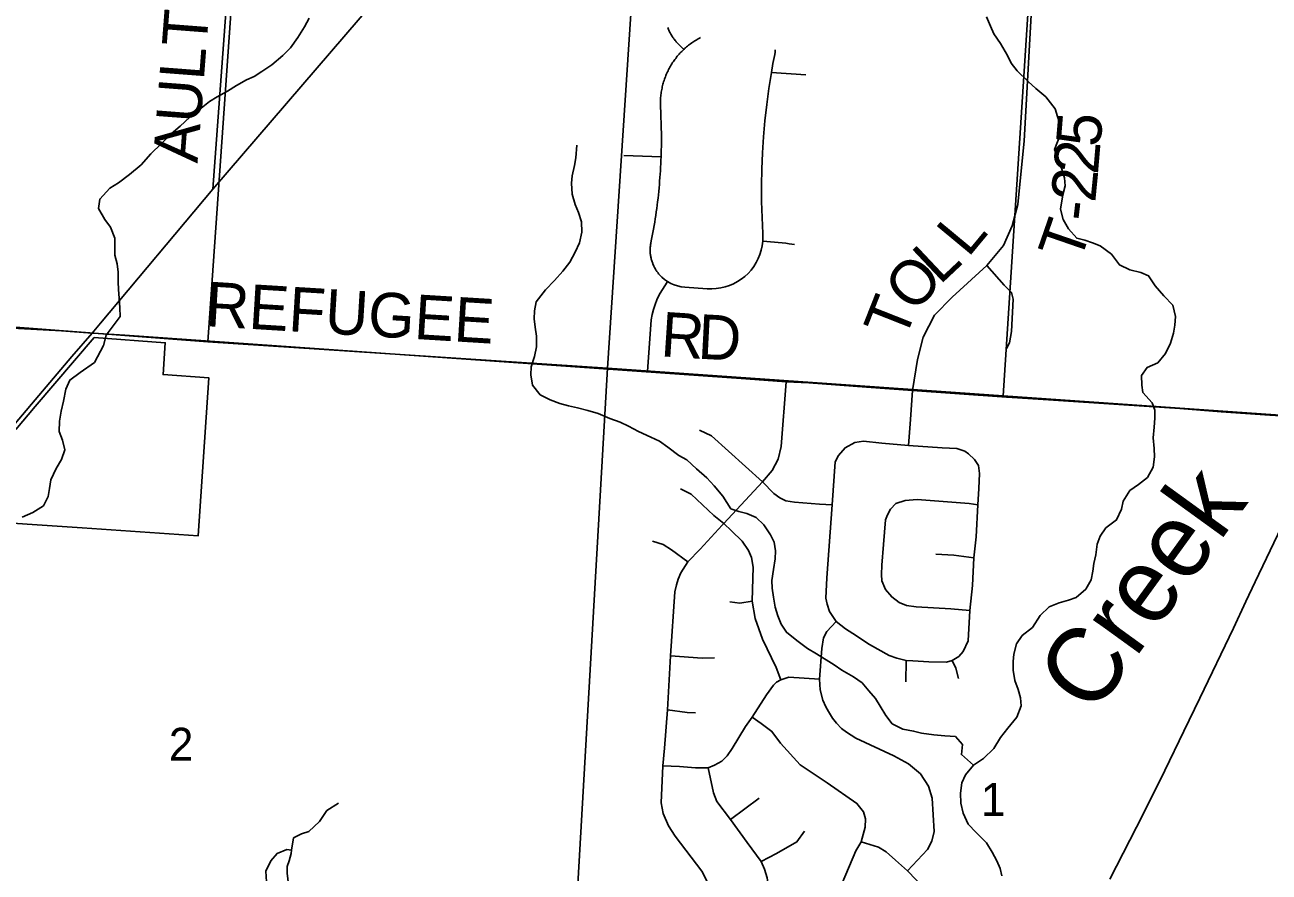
# Model space of a CAD drawing. Extents: x 0 to 34, y 0 to 22.
# Drawn here: x 6.46 to 8.044, y 15.327 to 16.406 of the extents above; entities that cross this region are included whole.
import ezdxf

# ---------------------------------------------------------------- set-up
doc = ezdxf.new("R2010")
doc.units = 0
for name, color, linetype in [('GM_X_Corporation', 7, 'Continuous'), ('GM_X_County_Road', 7, 'Continuous'), ('GM_X_County_Road_Text', 7, 'Continuous'), ('GM_X_Minor_Lake', 7, 'Continuous'), ('GM_X_Minor_River', 7, 'Continuous'), ('GM_X_Minor_River_Text', 7, 'Continuous'), ('GM_X_Section_Text', 7, 'Continuous'), ('GM_X_Township_Road', 7, 'Continuous'), ('GM_X_Township_Road_Text', 7, 'Continuous')]:
    doc.layers.add(name, color=color, linetype=linetype)

msp = doc.modelspace()

# ---------------------------------------------------------------- linework, layer by layer
at = {"layer": 'GM_X_Corporation'}
for points in [[(6.2535, 17.0548), (6.7642, 17.0207), (6.6929, 16.0021), (6.1806, 16.0412)], [(6.7642, 17.0207), (7.2687, 16.9868), (7.2018, 15.9686), (6.6929, 16.0021)], [(7.2687, 16.9868), (7.7715, 16.9516), (7.7055, 15.9334), (7.2018, 15.9686)], [(7.7715, 16.9516), (8.2797, 16.9169), (8.2166, 15.8976), (7.7055, 15.9334)], [(6.1806, 16.0412), (6.6929, 16.0021), (7.2018, 15.9686), (7.1441, 14.9641), (6.1096, 15.0446)], [(7.2018, 15.9686), (7.7055, 15.9334), (8.2166, 15.8976), (8.1497, 14.8881), (7.1441, 14.9641)]]:
    msp.add_lwpolyline(points, close=True, dxfattribs=at)
msp.add_lwpolyline([(6.3863, 15.7749), (6.5329, 15.7652), (6.6806, 15.7551), (6.694, 15.9564), (6.6358, 15.9605), (6.6386, 16.001), (6.5481, 16.0078), (6.4731, 15.9197), (6.4483, 15.8905)], dxfattribs=at)
at = {"layer": 'GM_X_County_Road'}
for points in [[(6.556, 16.0261), (6.6991, 16.1965), (6.9804, 16.5242), (7.026, 16.579), (7.046, 16.6041), (7.0557, 16.6231), (7.0747, 16.6658), (7.119, 16.7711), (7.177, 16.9074), (7.1885, 16.9354), (7.2006, 16.9746), (7.2668, 17.2151), (7.2825, 17.2751), (7.2901, 17.3083), (7.2922, 17.3236), (7.2973, 17.373), (7.3052, 17.4586), (7.3081, 17.496)], [(5.9168, 16.0609), (6.0471, 16.0509), (6.0534, 16.0504), (6.0669, 16.0492), (6.3448, 16.0254), (6.3457, 16.0254), (6.3647, 16.0237), (6.5064, 16.0163), (6.5453, 16.0133), (6.5533, 16.0128)], [(6.3283, 15.7523), (6.3975, 15.8384), (6.4005, 15.8421), (6.4098, 15.8539), (6.5194, 15.9836), (6.5453, 16.0133), (6.556, 16.0261)], [(6.5533, 16.0128), (6.5873, 16.0106), (7.3781, 15.9549), (7.4292, 15.951), (7.4581, 15.95), (7.5317, 15.9445), (7.5902, 15.9401), (7.7101, 15.9317), (7.717, 15.9313), (7.7697, 15.9277), (7.8593, 15.9217), (7.9306, 15.9171), (7.9832, 15.9128), (8.0451, 15.9087), (8.1468, 15.9026)]]:
    msp.add_lwpolyline(points, dxfattribs=at)
at = {"layer": 'GM_X_Minor_Lake'}
msp.add_lwpolyline([(6.7915, 15.3021), (6.7954, 15.3108), (6.794, 15.3252), (6.7937, 15.3339), (6.7965, 15.3411), (6.7989, 15.3506), (6.7993, 15.3548), (6.7932, 15.3556), (6.781, 15.3504), (6.773, 15.341), (6.7668, 15.3278), (6.7674, 15.3141), (6.7737, 15.3042), (6.7779, 15.3007), (6.7824, 15.2965)], dxfattribs=at)
at = {"layer": 'GM_X_Minor_River'}
for points in [[(7.6846, 16.4162), (7.6894, 16.404), (7.6939, 16.3945), (7.7021, 16.3819), (7.711, 16.367), (7.7158, 16.357), (7.7233, 16.3475), (7.7375, 16.3337), (7.7473, 16.3248), (7.7601, 16.3141), (7.772, 16.2988), (7.7749, 16.2892), (7.7797, 16.2752), (7.7777, 16.2645), (7.7711, 16.2472), (7.7748, 16.2376), (7.7799, 16.2235), (7.7839, 16.211), (7.7846, 16.2007), (7.7818, 16.1894), (7.7786, 16.1712)], [(6.8217, 16.4142), (6.8159, 16.4032), (6.8074, 16.3896), (6.7982, 16.3764), (6.7882, 16.3667), (6.7741, 16.3551), (6.7615, 16.3465), (6.7519, 16.3401), (6.742, 16.3357), (6.7295, 16.3286), (6.718, 16.3215), (6.7047, 16.314), (6.6951, 16.3084), (6.6799, 16.2965), (6.6699, 16.2882), (6.6577, 16.277), (6.6462, 16.2672), (6.634, 16.2548), (6.6202, 16.2417), (6.6079, 16.2274), (6.593, 16.2154), (6.5789, 16.2045), (6.5682, 16.1978), (6.5552, 16.1839), (6.5535, 16.1721), (6.5617, 16.158), (6.5688, 16.1481), (6.5743, 16.134), (6.5742, 16.1226), (6.5745, 16.1127), (6.5774, 16.1013), (6.5784, 16.0907), (6.5786, 16.0785), (6.5789, 16.0687), (6.5799, 16.0576), (6.5809, 16.0455), (6.5812, 16.0345), (6.5635, 16.0104), (6.56, 15.9975), (6.5484, 15.9756), (6.5301, 15.9629), (6.5171, 15.9535), (6.512, 15.9418), (6.5088, 15.9267), (6.506, 15.9138), (6.504, 15.9009), (6.5035, 15.888), (6.5079, 15.877), (6.5108, 15.8644), (6.5065, 15.8523), (6.4996, 15.8406), (6.493, 15.8263), (6.4913, 15.8153), (6.4893, 15.8051), (6.4835, 15.7934), (6.4698, 15.7848), (6.4565, 15.7788)], [(7.6679, 15.463), (7.6525, 15.4764), (7.6538, 15.4893), (7.6448, 15.4993), (7.6312, 15.5002), (7.6172, 15.5015), (7.6017, 15.5035), (7.5915, 15.5063), (7.5779, 15.5087), (7.5643, 15.5157), (7.5561, 15.526), (7.549, 15.5382), (7.5431, 15.5478), (7.5345, 15.5574), (7.5259, 15.5677), (7.515, 15.5754), (7.5003, 15.5839), (7.4905, 15.5908), (7.4679, 15.6047), (7.4563, 15.6117), (7.4427, 15.6217), (7.4296, 15.6321), (7.4229, 15.6424), (7.4188, 15.6531), (7.4151, 15.6641), (7.413, 15.677), (7.4116, 15.6884), (7.411, 15.6983), (7.413, 15.7123), (7.4154, 15.7256), (7.4159, 15.7358), (7.4141, 15.7469), (7.4093, 15.7564), (7.4007, 15.769), (7.391, 15.7782), (7.3793, 15.7833), (7.3691, 15.786), (7.3589, 15.7896), (7.3485, 15.8056), (7.3376, 15.8186), (7.3283, 15.829), (7.3151, 15.8405), (7.3028, 15.852), (7.2926, 15.8574), (7.2787, 15.8678), (7.2682, 15.8755), (7.2569, 15.8806), (7.2414, 15.8879), (7.2286, 15.8945), (7.218, 15.8996), (7.2048, 15.9046), (7.1898, 15.9109), (7.1769, 15.9148), (7.1637, 15.918), (7.152, 15.9204), (7.141, 15.9235), (7.1286, 15.9282), (7.1161, 15.9348), (7.1064, 15.947), (7.1043, 15.96), (7.1044, 15.9702), (7.1087, 15.9834), (7.1115, 15.9959), (7.1113, 16.0092), (7.1095, 16.0206), (7.1085, 16.0313), (7.109, 16.0415), (7.111, 16.0529), (7.1229, 16.0683), (7.1344, 16.0803), (7.1451, 16.092), (7.1536, 16.1037), (7.1605, 16.1165), (7.166, 16.1282), (7.1691, 16.1418), (7.1685, 16.1551), (7.1649, 16.1669), (7.1604, 16.1772), (7.1568, 16.1902), (7.1558, 16.2042), (7.1567, 16.2137), (7.1598, 16.2266), (7.1614, 16.2364), (7.1628, 16.2527)], [(7.7786, 16.1712), (7.7819, 16.1579), (7.7889, 16.146), (7.7994, 16.1341), (7.8096, 16.1314), (7.8194, 16.1282), (7.8292, 16.1243), (7.8435, 16.1136), (7.8536, 16.1002), (7.8668, 16.094), (7.8811, 16.0904), (7.8909, 16.0861), (7.8991, 16.0735), (7.9104, 16.0609), (7.9216, 16.049), (7.9252, 16.0342), (7.9244, 16.0232), (7.9227, 16.0133), (7.9188, 16.0004), (7.9122, 15.9872), (7.9026, 15.9752), (7.8889, 15.9693), (7.882, 15.9591), (7.8822, 15.9469), (7.8837, 15.9374), (7.8953, 15.9244), (7.8986, 15.9149), (7.8988, 15.905), (7.898, 15.8933), (7.8967, 15.88), (7.898, 15.8663), (7.8983, 15.8557), (7.8966, 15.8424), (7.8893, 15.8292), (7.8782, 15.8206), (7.8668, 15.8127), (7.8583, 15.7992), (7.8563, 15.7889), (7.8501, 15.7753), (7.8363, 15.7652), (7.829, 15.7547), (7.8255, 15.7445), (7.8235, 15.7308), (7.8211, 15.7198), (7.8198, 15.71), (7.8178, 15.699), (7.8109, 15.6869), (7.7986, 15.6764), (7.7888, 15.6731), (7.777, 15.6695), (7.7644, 15.6646), (7.7526, 15.6534), (7.7429, 15.6383), (7.7299, 15.6282), (7.7226, 15.6176), (7.7191, 15.6044), (7.7182, 15.5949), (7.7185, 15.5839), (7.7206, 15.5706), (7.7246, 15.5592), (7.7279, 15.5485), (7.7286, 15.5386), (7.7231, 15.5239), (7.7116, 15.51), (7.7024, 15.4983), (7.6939, 15.484), (7.6805, 15.4716), (7.6679, 15.463), (7.6576, 15.4506), (7.6529, 15.4404), (7.6512, 15.4271), (7.6519, 15.4146), (7.6548, 15.4016), (7.6611, 15.3879), (7.6712, 15.3772), (7.6843, 15.3641), (7.6917, 15.3523), (7.6977, 15.3409), (7.7017, 15.3313), (7.7039, 15.3218)], [(6.7993, 15.3548), (6.8021, 15.3703), (6.812, 15.3755), (6.8215, 15.3784), (6.8349, 15.3912), (6.8445, 15.4051), (6.859, 15.4145)]]:
    msp.add_lwpolyline(points, dxfattribs=at)
at = {"layer": 'GM_X_Township_Road'}
for p, q in [((7.4105, 16.345), (7.4545, 16.3421)), ((7.2226, 16.2394), (7.27, 16.2377)), ((7.5823, 15.5961), (7.5816, 15.5691)), ((7.3584, 15.3939), (7.3949, 15.4207))]:
    msp.add_line(p, q, dxfattribs=at)
for points in [[(6.6991, 16.1965), (6.737, 16.7093), (6.7461, 16.8276), (6.7553, 16.9507), (6.7768, 17.2757), (6.7924, 17.4238), (6.8004, 17.5319)], [(7.5902, 15.9401), (7.5965, 15.9796), (7.6036, 16.0079), (7.6181, 16.0362), (7.6409, 16.0588), (7.6848, 16.0992), (7.706, 16.125), (7.7171, 16.1497), (7.7242, 16.1769), (7.7323, 16.2582), (7.7673, 16.885), (7.8067, 17.4568)], [(7.2988, 16.3745), (7.2894, 16.3844), (7.2886, 16.3852), (7.2879, 16.3861), (7.2871, 16.387), (7.2864, 16.3879), (7.2857, 16.3888), (7.285, 16.3898), (7.2844, 16.3908), (7.2837, 16.3917), (7.2831, 16.3927), (7.2825, 16.3938), (7.282, 16.3948), (7.2815, 16.3958), (7.2809, 16.3969), (7.2805, 16.3979), (7.28, 16.399), (7.2796, 16.4001), (7.2792, 16.4012), (7.2788, 16.4023)], [(7.2783, 16.0789), (7.2744, 16.0816), (7.2709, 16.0846), (7.2677, 16.088), (7.2669, 16.0889), (7.2662, 16.0898), (7.2655, 16.0907), (7.2648, 16.0916), (7.2641, 16.0926), (7.2635, 16.0936), (7.2629, 16.0946), (7.2623, 16.0956), (7.2617, 16.0966), (7.2612, 16.0977), (7.2607, 16.0987), (7.2602, 16.0998), (7.2597, 16.1009), (7.2593, 16.1019), (7.2589, 16.103), (7.2585, 16.1041), (7.2582, 16.1053), (7.2578, 16.1064), (7.2575, 16.1075), (7.2573, 16.1087), (7.257, 16.1098), (7.2568, 16.111), (7.2566, 16.1121), (7.2565, 16.1133), (7.2563, 16.1144), (7.2563, 16.1156), (7.2562, 16.1168), (7.2561, 16.1179), (7.2561, 16.1191), (7.2562, 16.1203), (7.2562, 16.1214), (7.2563, 16.1226), (7.2564, 16.1238), (7.2565, 16.1249), (7.2567, 16.1261), (7.2569, 16.1273), (7.2571, 16.1284), (7.258, 16.1327), (7.2588, 16.1371), (7.2596, 16.1414), (7.2604, 16.1457), (7.2611, 16.1501), (7.2619, 16.1544), (7.2625, 16.1588), (7.2632, 16.1631), (7.2638, 16.1675), (7.2644, 16.1719), (7.265, 16.1762), (7.2656, 16.1806), (7.2661, 16.185), (7.2666, 16.1894), (7.267, 16.1938), (7.2675, 16.1981), (7.2679, 16.2025), (7.2682, 16.2069), (7.2686, 16.2113), (7.2689, 16.2157), (7.2692, 16.2201), (7.2694, 16.2245), (7.2697, 16.2289), (7.2699, 16.2333), (7.27, 16.2377), (7.2702, 16.2422), (7.2703, 16.2466), (7.2704, 16.2511), (7.2704, 16.2555), (7.2704, 16.26), (7.2704, 16.2644), (7.2704, 16.2689), (7.2703, 16.2733), (7.2702, 16.2778), (7.2701, 16.2822), (7.2699, 16.2867), (7.2697, 16.2911), (7.2695, 16.2956), (7.2693, 16.3), (7.2692, 16.3017), (7.2691, 16.3034), (7.2691, 16.3051), (7.2691, 16.3067), (7.2692, 16.3084), (7.2692, 16.3101), (7.2693, 16.3118), (7.2694, 16.3135), (7.2696, 16.3152), (7.2698, 16.3168), (7.27, 16.3185), (7.2702, 16.3202), (7.2705, 16.3219), (7.2708, 16.3235), (7.2712, 16.3252), (7.2715, 16.3268), (7.2719, 16.3285), (7.2723, 16.3301), (7.2728, 16.3317), (7.2733, 16.3333), (7.2738, 16.3349), (7.2743, 16.3365), (7.2749, 16.3381), (7.2755, 16.3397), (7.2761, 16.3413), (7.2767, 16.3428), (7.2774, 16.3444), (7.2781, 16.3459), (7.2789, 16.3474), (7.2796, 16.3489), (7.2804, 16.3504), (7.2812, 16.3519), (7.2821, 16.3534), (7.2829, 16.3548), (7.2838, 16.3563), (7.2847, 16.3577), (7.2857, 16.3591), (7.2866, 16.3605), (7.2876, 16.3618), (7.2886, 16.3632), (7.2897, 16.3645), (7.2907, 16.3658), (7.2918, 16.3671), (7.2929, 16.3684), (7.2941, 16.3696), (7.2952, 16.3709), (7.2964, 16.3721), (7.2976, 16.3733), (7.2988, 16.3745), (7.3, 16.3756), (7.3012, 16.3767), (7.3025, 16.3778), (7.3037, 16.3788), (7.305, 16.3798), (7.3063, 16.3809), (7.3076, 16.3818), (7.309, 16.3828), (7.3103, 16.3838), (7.3117, 16.3847), (7.3131, 16.3856), (7.3145, 16.3864), (7.3159, 16.3873), (7.3173, 16.3881), (7.3188, 16.3889), (7.3202, 16.3897)], [(7.2783, 16.0789), (7.2823, 16.0766), (7.2866, 16.0747), (7.291, 16.0733), (7.2955, 16.0723), (7.3001, 16.0717), (7.3289, 16.0697), (7.3346, 16.0695), (7.3403, 16.0699), (7.346, 16.0707), (7.3516, 16.072), (7.357, 16.0738), (7.3623, 16.0761), (7.3673, 16.0788), (7.3721, 16.0819), (7.3766, 16.0854), (7.3808, 16.0893), (7.3847, 16.0936), (7.3881, 16.0982), (7.3912, 16.103), (7.3938, 16.1081), (7.3959, 16.1134), (7.3976, 16.1189), (7.3989, 16.1245), (7.3996, 16.1302), (7.3998, 16.135), (7.3997, 16.1399), (7.3987, 16.1605), (7.3981, 16.181), (7.398, 16.2016), (7.3984, 16.2222), (7.3992, 16.2428), (7.4005, 16.2633), (7.4023, 16.2838), (7.4046, 16.3043), (7.4073, 16.3247), (7.4105, 16.345), (7.4125, 16.3566), (7.4147, 16.3681), (7.4152, 16.3711), (7.4155, 16.3741)], [(7.3996, 16.1302), (7.4244, 16.1281), (7.4288, 16.1276), (7.4333, 16.127), (7.4399, 16.126)], [(7.7101, 15.9937), (7.7136, 16.0008), (7.7161, 16.0154), (7.7186, 16.0563), (7.7161, 16.0649), (7.707, 16.0745), (7.6848, 16.0992)], [(7.2526, 15.9642), (7.2526, 15.9649), (7.2568, 16.0237), (7.2575, 16.0303), (7.2586, 16.0369), (7.2602, 16.0433), (7.2623, 16.0496), (7.2648, 16.0558), (7.2677, 16.0618), (7.2711, 16.0675), (7.2757, 16.0749), (7.2783, 16.0789)], [(7.348, 15.7686), (7.35, 15.7708), (7.3991, 15.8238), (7.4113, 15.8382), (7.4191, 15.8528), (7.423, 15.869), (7.4292, 15.951)], [(7.5851, 15.8702), (7.5877, 15.903), (7.5902, 15.9401)], [(8.1468, 15.9026), (8.1158, 15.8593), (8.0985, 15.8336), (8.0869, 15.8153), (8.0774, 15.7994), (8.07, 15.7858), (8.0602, 15.7664), (8.0266, 15.6966), (8.0147, 15.6714), (7.999, 15.6376), (7.956, 15.5482), (7.9359, 15.5063), (7.9115, 15.4562), (7.8839, 15.4007), (7.8417, 15.3177)], [(7.319, 15.8897), (7.3343, 15.8824), (7.3991, 15.8238), (7.4138, 15.8089), (7.4214, 15.8035), (7.429, 15.7998), (7.44, 15.7977), (7.4716, 15.7955), (7.4879, 15.7943)], [(7.4959, 15.8574), (7.5043, 15.8672), (7.5168, 15.8738), (7.5279, 15.8757), (7.5512, 15.8732), (7.5851, 15.8702), (7.628, 15.8672), (7.6468, 15.8664), (7.6567, 15.8628), (7.6617, 15.8596), (7.6691, 15.8523)], [(7.4959, 15.8574), (7.4917, 15.8494), (7.4879, 15.7943), (7.4811, 15.7017), (7.4799, 15.6755), (7.4814, 15.6679), (7.4845, 15.6585), (7.4928, 15.6459)], [(7.6691, 15.8523), (7.6741, 15.8447), (7.6757, 15.8342), (7.6748, 15.8154), (7.6732, 15.7945), (7.6712, 15.7539), (7.6683, 15.727), (7.6664, 15.6918), (7.6633, 15.6597), (7.6611, 15.6213), (7.6547, 15.6075)], [(7.3596, 15.7614), (7.35, 15.7708), (7.3372, 15.781), (7.3084, 15.8079), (7.2948, 15.8149)], [(7.6732, 15.7945), (7.6623, 15.7961), (7.5963, 15.8012), (7.5808, 15.8001), (7.5691, 15.7961), (7.5623, 15.789), (7.5582, 15.7816), (7.5557, 15.7755), (7.5531, 15.7438), (7.551, 15.7176), (7.5509, 15.7056), (7.551, 15.6977), (7.5556, 15.6865), (7.5637, 15.6772), (7.5731, 15.6699), (7.5827, 15.6664), (7.5947, 15.6645), (7.6392, 15.6621), (7.6633, 15.6597)], [(7.3309, 15.3104), (7.322, 15.328), (7.2878, 15.3725), (7.2795, 15.3856), (7.2728, 15.4012), (7.2703, 15.4149), (7.2724, 15.462), (7.2745, 15.4847), (7.2782, 15.5333), (7.2822, 15.6022), (7.2876, 15.6837), (7.2898, 15.6926), (7.2918, 15.6998), (7.295, 15.7077), (7.304, 15.7221), (7.3197, 15.7382), (7.348, 15.7686)], [(7.4226, 15.5718), (7.4164, 15.5874), (7.3993, 15.6234), (7.3898, 15.6498), (7.3861, 15.6717), (7.3865, 15.6865), (7.3874, 15.7149), (7.3852, 15.7275), (7.3813, 15.7365), (7.3732, 15.7481), (7.3596, 15.7614)], [(7.259, 15.7483), (7.2728, 15.7441), (7.2833, 15.7371), (7.304, 15.7221)], [(7.6198, 15.7318), (7.6429, 15.7304), (7.6683, 15.727)], [(7.3576, 15.6709), (7.3704, 15.6692), (7.3861, 15.6717)], [(7.5838, 15.3284), (7.6095, 15.3556), (7.6149, 15.3663), (7.6178, 15.3785), (7.6154, 15.4209), (7.6105, 15.4361), (7.6003, 15.4517), (7.5852, 15.4648), (7.5664, 15.4746), (7.5182, 15.4972), (7.5062, 15.505), (7.4996, 15.5097), (7.4933, 15.5165), (7.4884, 15.5226), (7.4831, 15.5311), (7.4799, 15.537), (7.4762, 15.5455), (7.4724, 15.5589), (7.4716, 15.5725), (7.4748, 15.6115), (7.4768, 15.625), (7.4811, 15.6333), (7.4928, 15.6459)], [(7.4928, 15.6459), (7.5048, 15.6367), (7.5142, 15.6305), (7.5356, 15.6168), (7.5605, 15.6025), (7.5702, 15.599), (7.5823, 15.5961), (7.5907, 15.5957), (7.6111, 15.5945), (7.6335, 15.5943), (7.6406, 15.5963), (7.6492, 15.6013), (7.6547, 15.6075)], [(7.2822, 15.6022), (7.3224, 15.5993), (7.3379, 15.5996)], [(7.6406, 15.5963), (7.6452, 15.5865), (7.6489, 15.5731)], [(7.2724, 15.462), (7.2934, 15.461), (7.3139, 15.4595), (7.3299, 15.4597), (7.338, 15.4631), (7.3472, 15.468), (7.3542, 15.4749), (7.3607, 15.484), (7.3776, 15.512), (7.3861, 15.5239), (7.4044, 15.5526), (7.413, 15.5647), (7.417, 15.5686), (7.4226, 15.5718), (7.4325, 15.5749), (7.4716, 15.5725)], [(7.2782, 15.5333), (7.3031, 15.5301), (7.314, 15.5295)], [(7.3861, 15.5239), (7.3975, 15.516), (7.4112, 15.506), (7.4222, 15.4909), (7.4473, 15.4634), (7.4814, 15.4404), (7.5195, 15.4141), (7.5276, 15.4033), (7.5303, 15.3945), (7.5301, 15.3841), (7.5247, 15.3654), (7.5242, 15.3645)], [(7.3299, 15.4597), (7.3366, 15.4276), (7.3412, 15.4166), (7.3584, 15.3939), (7.3796, 15.3642), (7.3975, 15.3404), (7.4018, 15.3304), (7.4053, 15.3195), (7.4068, 15.3083), (7.403, 15.2678), (7.4032, 15.2593), (7.4053, 15.2507), (7.4099, 15.2397), (7.415, 15.2331), (7.4268, 15.2237), (7.45, 15.2045)], [(7.3975, 15.3404), (7.4168, 15.3502), (7.4429, 15.3652), (7.4527, 15.379)], [(7.5242, 15.3645), (7.5181, 15.3536), (7.4867, 15.2795), (7.4597, 15.2195), (7.45, 15.2045), (7.4493, 15.2037)], [(7.5247, 15.3654), (7.547, 15.3584), (7.5567, 15.3525), (7.5686, 15.3417), (7.5838, 15.3284), (7.6176, 15.2932)]]:
    msp.add_lwpolyline(points, dxfattribs=at)

# ---------------------------------------------------------------- texts
at = {"layer": 'GM_X_County_Road_Text'}
for s, height, rotation, p in [('REFUGEE', 0.05682, 356.4898, (6.6891, 16.0222)), ('R', 0.0568, 356.2467, (7.2685, 15.9838)), ('D', 0.0568, 357.0592, (7.3159, 15.9807))]:
    msp.add_text(s, height=height, rotation=rotation, dxfattribs=at).set_placement(p)
at = {"layer": 'GM_X_Minor_River_Text'}
msp.add_text('Creek', height=0.0947, rotation=54.088, dxfattribs=at).set_placement((7.8202, 15.5242))
at = {"layer": 'GM_X_Section_Text'}
for s, p in [('2', (6.6432, 15.4686)), ('1', (7.6773, 15.3983))]:
    msp.add_text(s, height=0.0419, rotation=0, dxfattribs=at).set_placement(p)
at = {"layer": 'GM_X_Township_Road_Text'}
for s, height, rotation, p in [('AULT', 0.05682, 85.6205, (6.6796, 16.2291)), ('5', 0.0568, 85.2724, (7.8293, 16.2494)), ('2', 0.0568, 85.0963, (7.8262, 16.2143)), ('2', 0.0568, 84.3829, (7.8228, 16.1787)), ('-', 0.0568, 83.2346, (7.8199, 16.1543)), ('L', 0.0568, 50.3085, (7.6609, 16.1084)), ('T', 0.0568, 70.9484, (7.803, 16.1012)), ('L', 0.0568, 43.3179, (7.6248, 16.0737)), ('O', 0.0568, 48.5235, (7.5926, 16.0372)), ('T', 0.0568, 68.4357, (7.5797, 16.0021))]:
    msp.add_text(s, height=height, rotation=rotation, dxfattribs=at).set_placement(p)

doc.saveas('drawing.dxf')
